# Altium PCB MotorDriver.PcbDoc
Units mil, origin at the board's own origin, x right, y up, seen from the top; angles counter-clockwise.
Board outline 4000 x 4995 mil, 4 copper layers (Top Layer, VCC, GND, Bottom Layer), stack 23.756 mil thick; 93 components, 73 nets, 281 pads, 38 vias.
Unrouted connection lines stored in the file: 23.
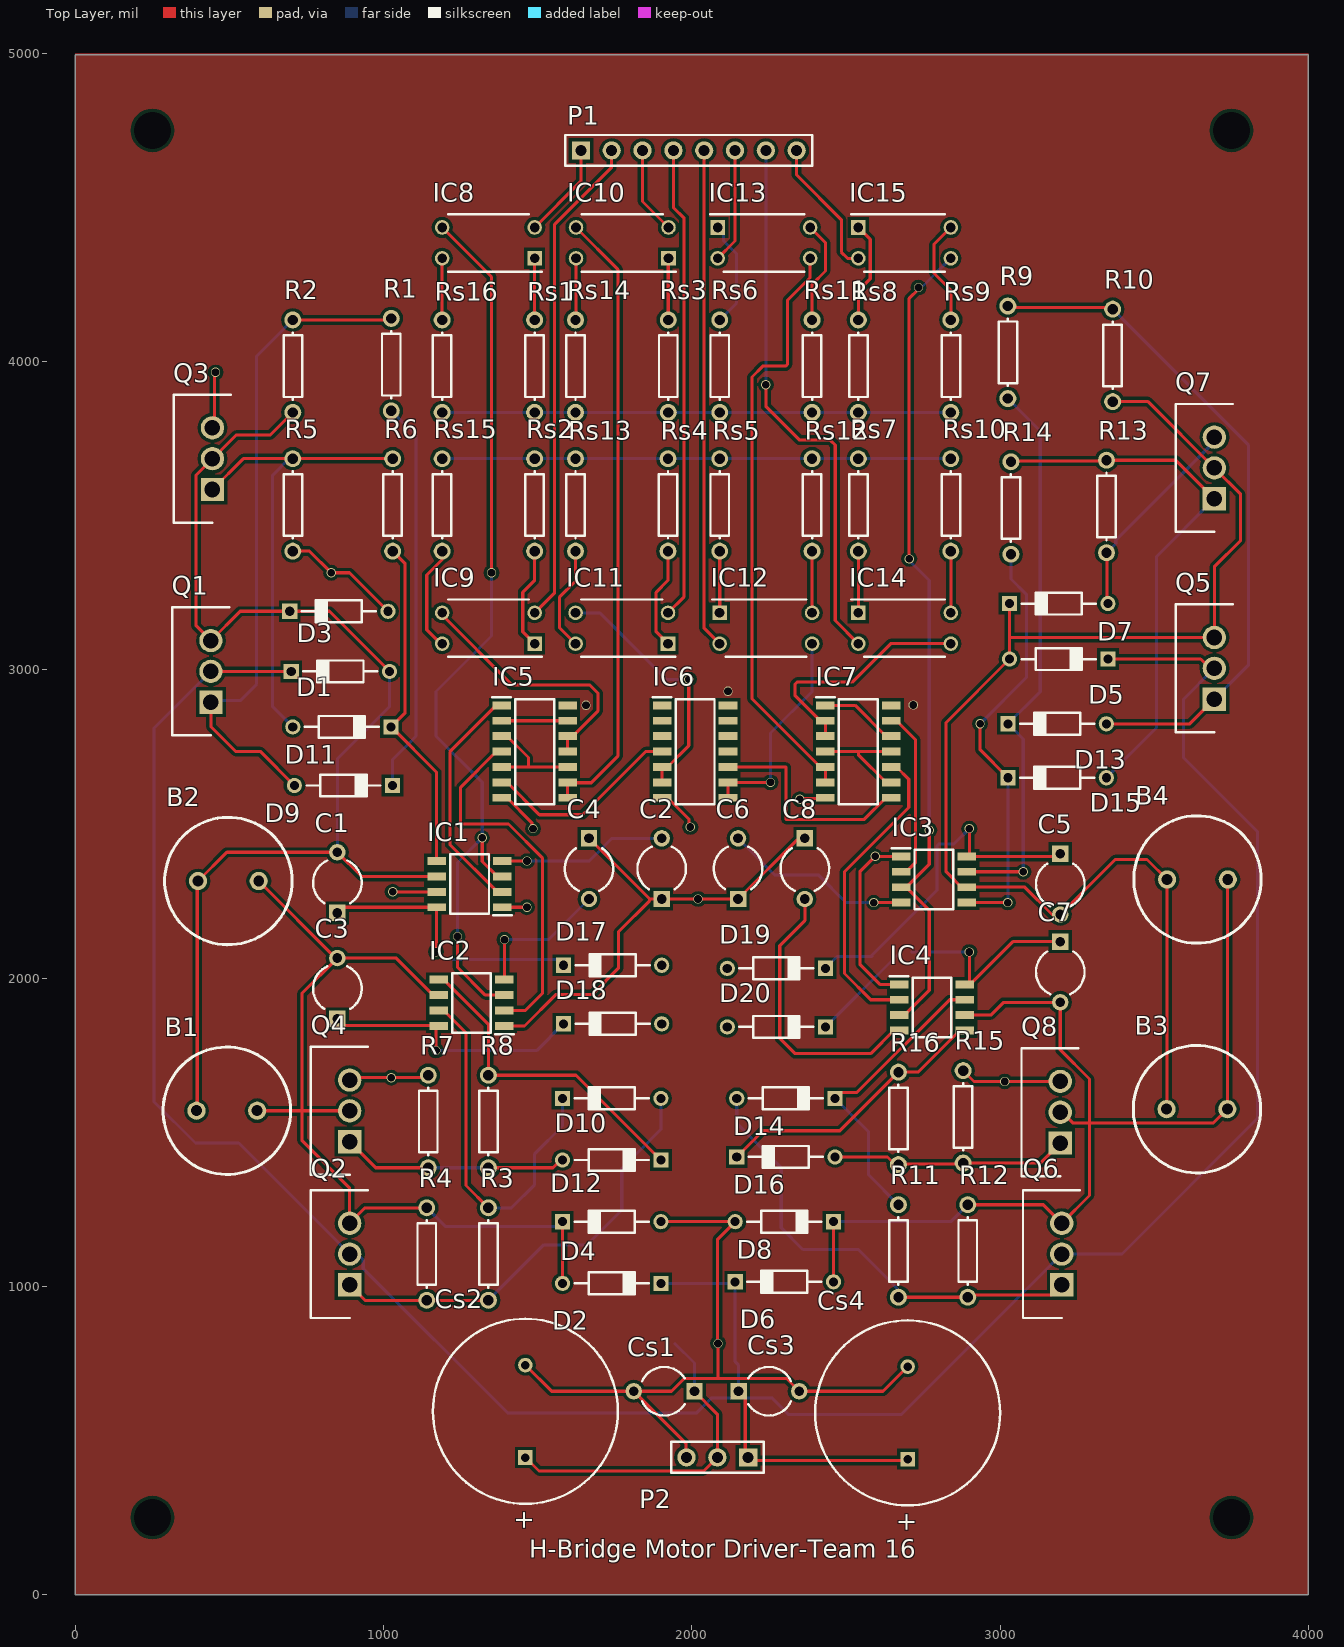
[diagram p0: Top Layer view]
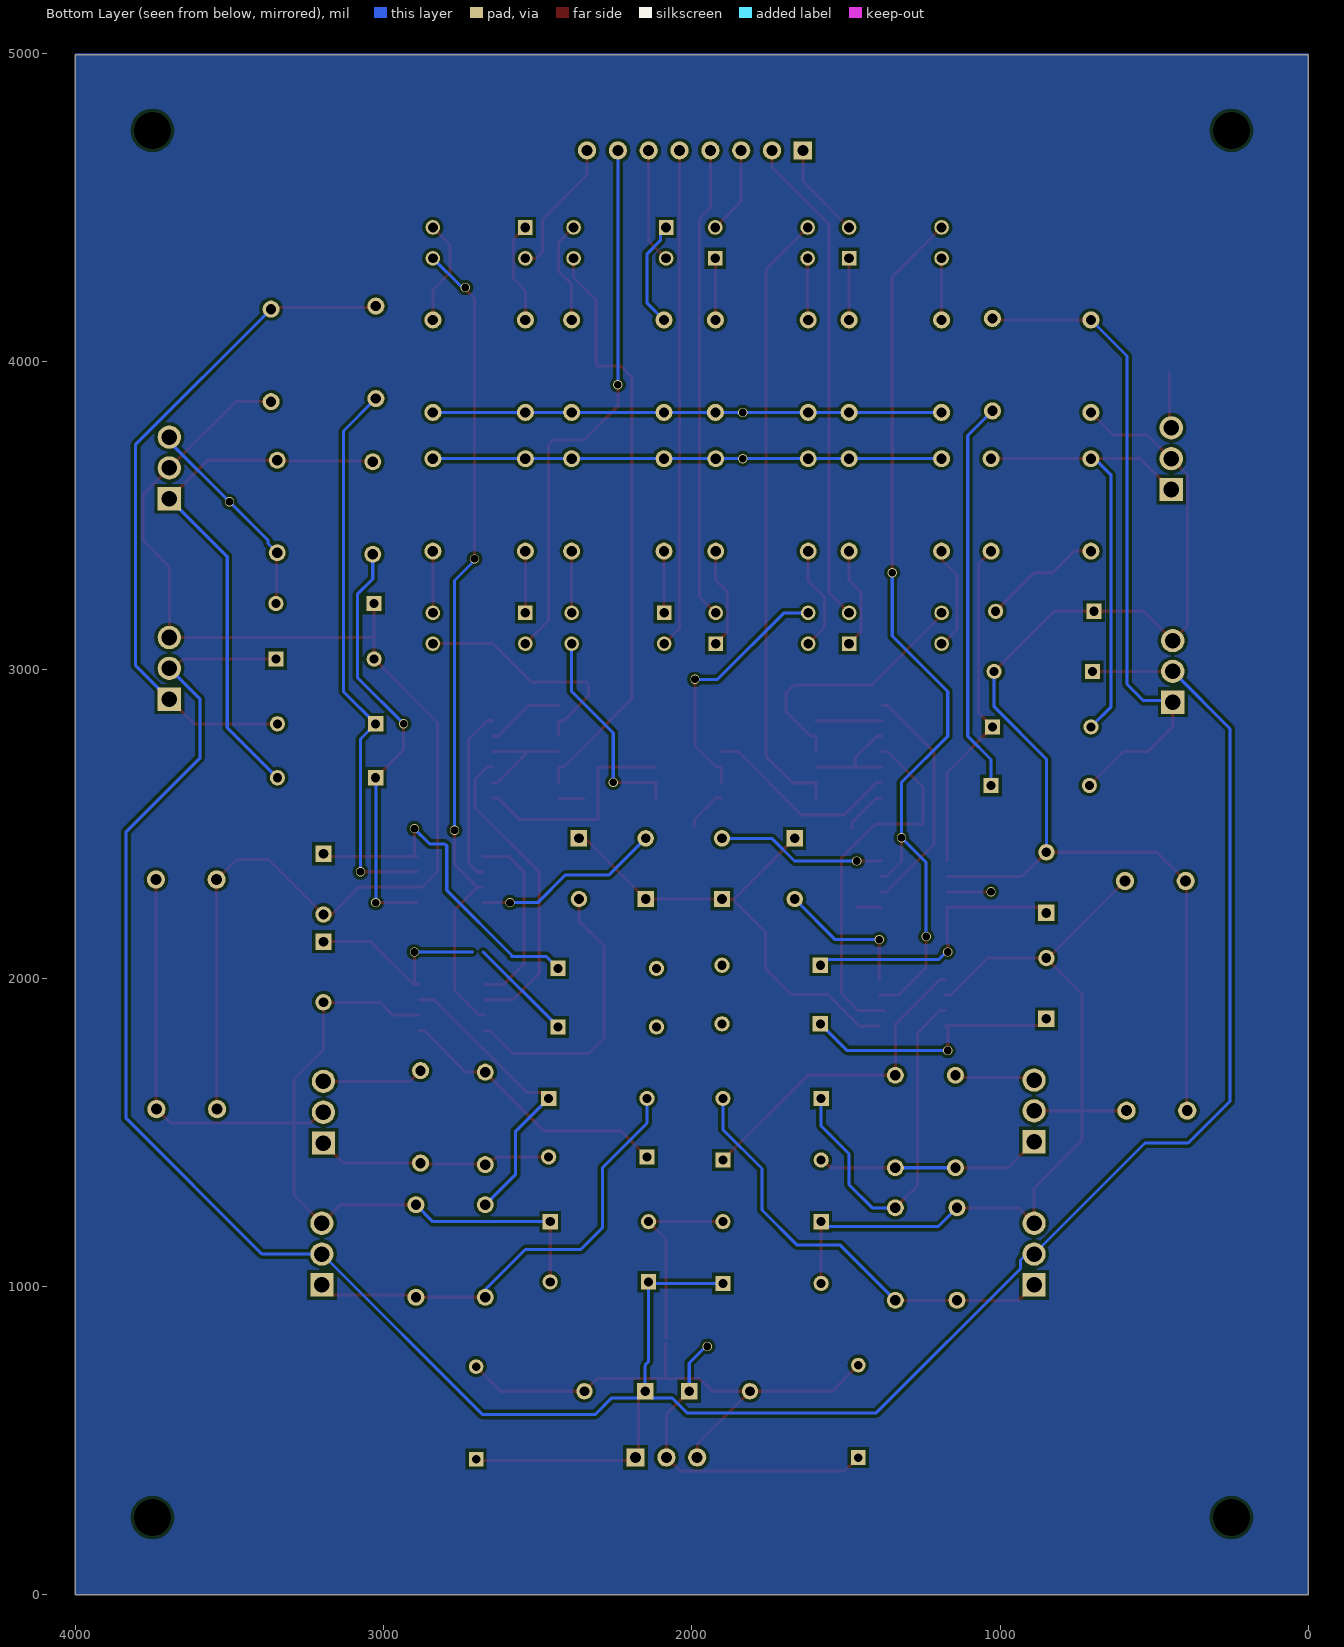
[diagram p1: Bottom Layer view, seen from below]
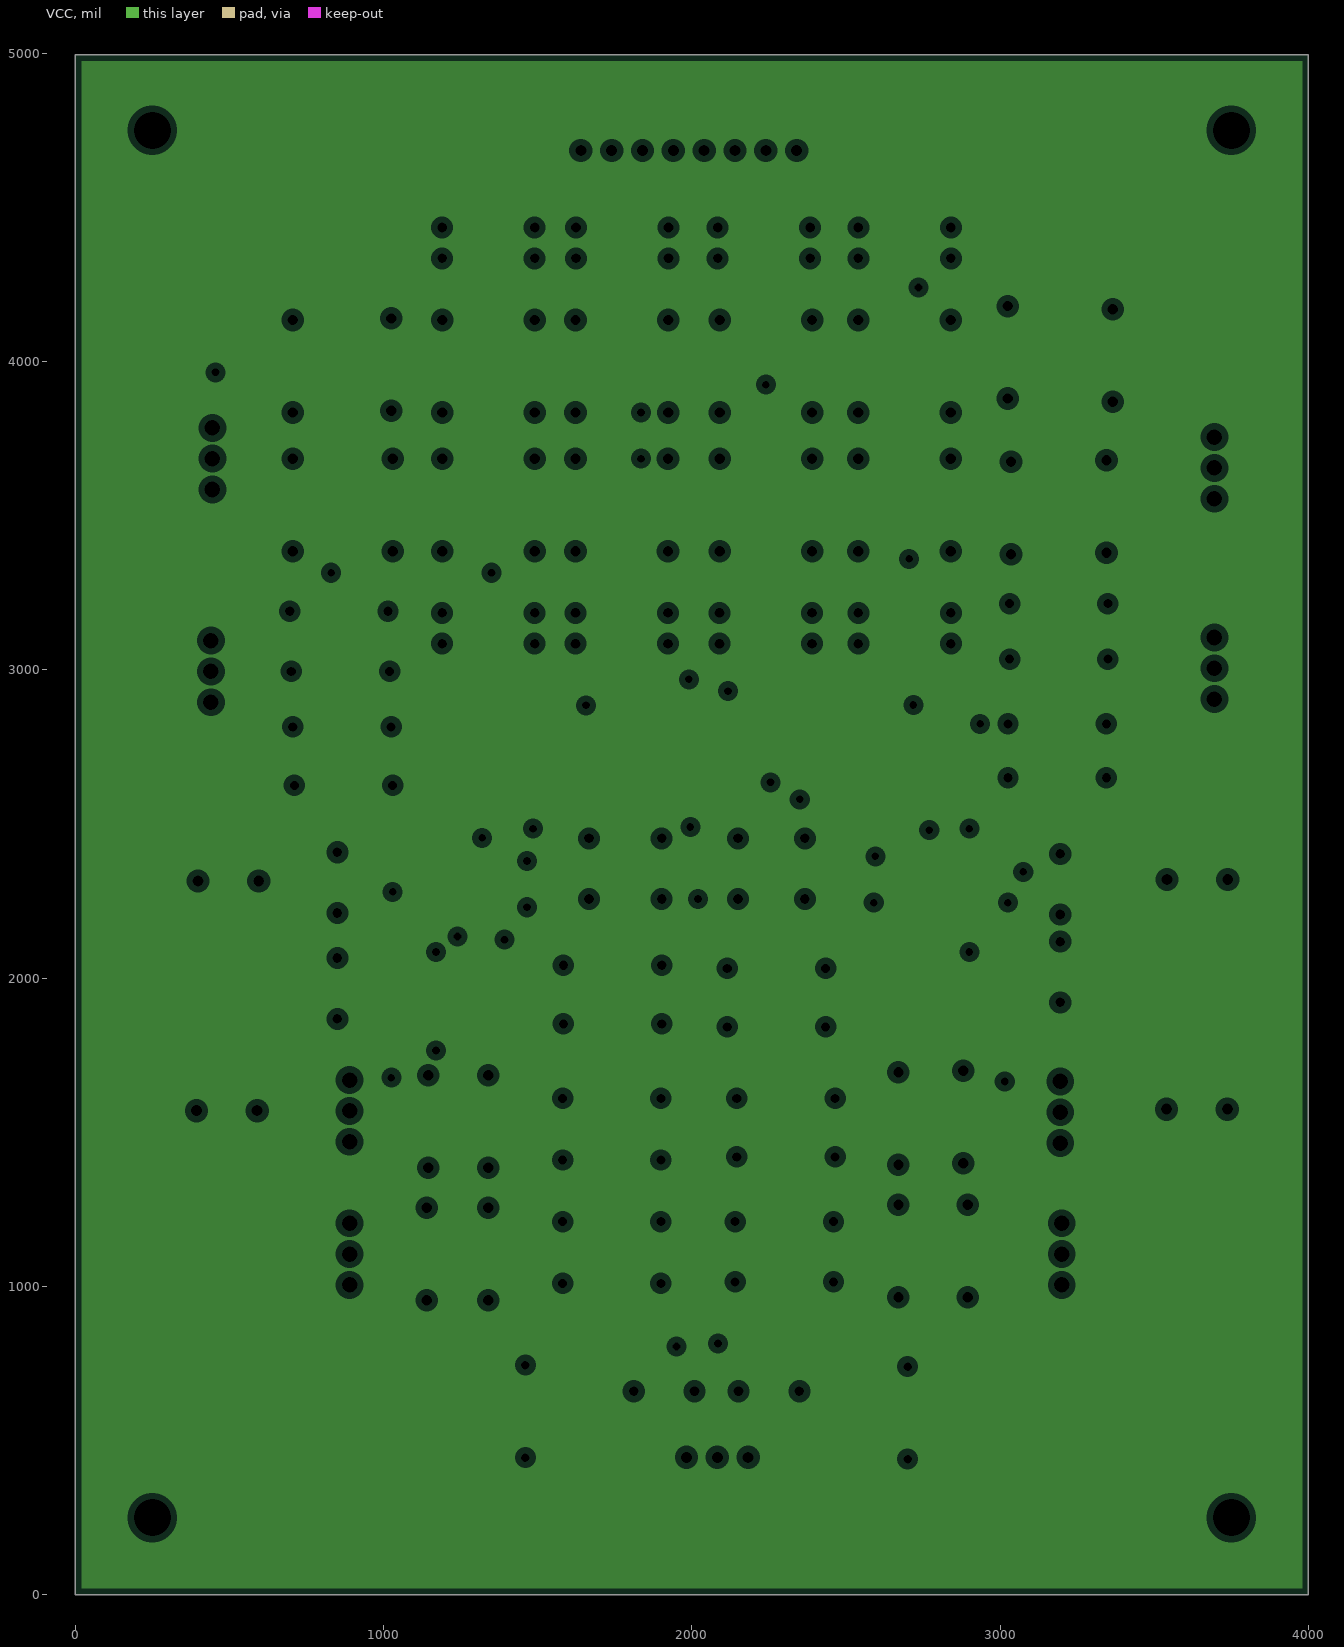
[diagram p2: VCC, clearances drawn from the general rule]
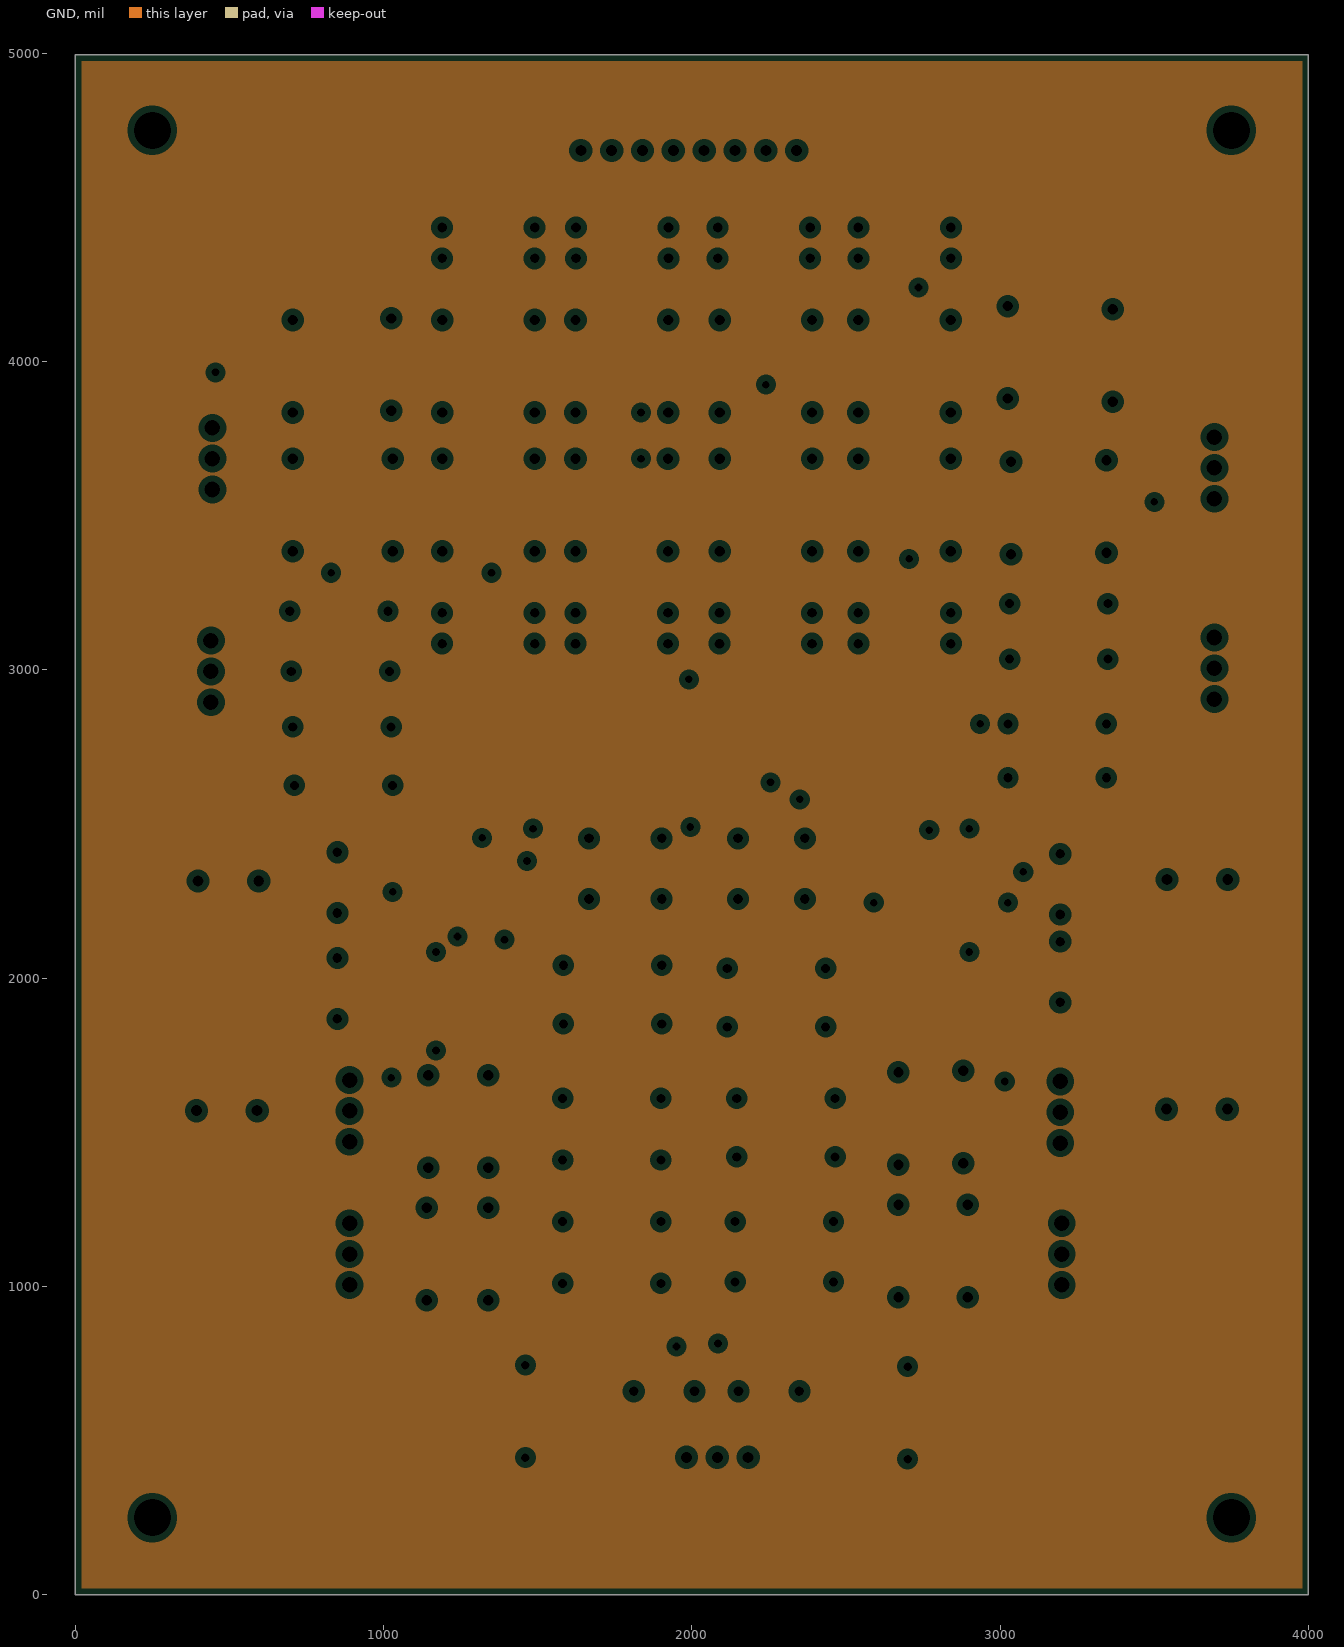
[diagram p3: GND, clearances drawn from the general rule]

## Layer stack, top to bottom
Top Solder: solder mask 0.4, Solder Resist, Dk 3.5
Top Layer: signal copper 1.4
Dielectric 2: prepreg 2.8, PP-006, Dk 4.1
VCC: plane copper 1.3778
Dielectric 1: dielectric 12.6, FR-4, Dk 4.8
GND: plane copper 1.3778
Dielectric 3: prepreg 2.8, PP-006, Dk 4.1
Bottom Layer: signal copper 1.4
Bottom Solder: solder mask 0.4, Solder Resist, Dk 3.5

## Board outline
0,0 4000,0 4000,4995 0,4995

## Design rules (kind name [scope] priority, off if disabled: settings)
Clearance [All] p1: gap=10 ignorepadtopadclearanceinfootprint=FALSE except(0: Arc-Hole Track-Hole SMDPad-Hole THPad-Hole Via-Hole Fill-Hole Poly-Hole Region-Hole Text-Hole)
PlaneClearance [All] p1: clearance=20
PlaneConnect [All] p1: planeconnectstyle=Relief reliefexpansion=20 reliefentries=4 reliefconductorwidth=10 reliefairgap=10
PolygonConnect [All] p1: connectstyle=Relief reliefconductorwidth=10 reliefentries=4 polygonreliefangle="90 Angle" airgapwidth=10
RoutingVias [All] p1: holewidth=28 width=50 viastyle="Through Hole" minholewidth=28 minwidth=50 maxholewidth=28 maxwidth=50
SolderMaskExpansion [All] p1: expansion=4
Width [All] p1: maxlimit=10 minlimit=10 preferedwidth=10
28 further rules are at their usual default settings.

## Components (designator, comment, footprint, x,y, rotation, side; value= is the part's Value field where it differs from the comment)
B1 "Motor" RB5-10.5 491.57,1570 r0 top
B2 "Motor" RB5-10.5 496.57,2315 r0 top
B3 "Motor" RB5-10.5 3638.43,1575 r0 top
B4 "Motor" RB5-10.5 3640,2320 r0 top
C1 "" CAPR5-4X5 850,2310 r90 top value=1.5uF
C2 "" CAPR5-4X5 1902.2,2355 r90 top value=100nF
C3 "" CAPR5-4X5 850,1966.57 r90 top value=1.5uF
C4 "" CAPR5-4X5 1666.38,2355 r270 top value=100nF
C5 "" CAPR5-4X5 3195,2305 r270 top value=1.5uF
C6 "" CAPR5-4X5 2149.92,2355 r90 top value=100nF
C7 "" CAPR5-4X5 3195,2020 r270 top value=1.5uF
C8 "" CAPR5-4X5 2366.38,2355 r270 top value=100nF
Cs1 "" CAPR5-4X5 1910,660 r180 top value=100nF
Cs2 "" RB7.6-15 1460,595 r270 top value=100uF
Cs3 "" CAPR5-4X5 2250,660 r0 top value=100nF
Cs4 "" RB7.6-15 2700,590 r270 top value=100uF
D1 "1N5711" DIOAD810W51L378D176P 860,2995 r0 top
D2 "1N5711" DIOAD810W51L378D176P 1740,1010 r180 top
D3 "1N5711" DIOAD810W51L378D176P 855,3190 r0 top
D4 "1N5711" DIOAD810W51L378D176P 1740,1210 r0 top
D5 "1N5711" DIOAD810W51L378D176P 3190,3035 r180 top
D6 "1N5711" DIOAD810W51L378D176P 2300,1015 r0 top
D7 "1N5711" DIOAD810W51L378D176P 3190,3215 r0 top
D8 "1N5711" DIOAD810W51L378D176P 2300,1210 r180 top
D9 "1N5711" DIOAD810W51L378D176P 870,2625 r180 top
D10 "1N5711" DIOAD810W51L378D176P 1740,1610 r0 top
D11 "1N5711" DIOAD810W51L378D176P 865,2815 r180 top
D12 "1N5711" DIOAD810W51L378D176P 1740,1410 r180 top
D13 "1N5711" DIOAD810W51L378D176P 3185,2825 r0 top
D14 "1N5711" DIOAD810W51L378D176P 2305,1610 r180 top
D15 "1N5711" DIOAD810W51L378D176P 3185,2650 r0 top
D16 "1N5711" DIOAD810W51L378D176P 2305,1420 r0 top
D17 "1N5711" DIOAD810W51L378D176P 1742.76,2041.85 r0 top
D18 "1N5711" DIOAD810W51L378D176P 1742.76,1851.85 r0 top
D19 "1N5711" DIOAD810W51L378D176P 2274.37,2031.85 r180 top
D20 "1N5711" DIOAD810W51L378D176P 2274.37,1841.85 r180 top
IC1 "IR2104SPBF" SOIC127P600X175-8N 1278.98,2305 r180 top
IC2 "IR2104SPBF" SOIC127P600X175-8N 1285.28,1920 r180 top
IC3 "IR2104SPBF" SOIC127P600X175-8N 2785.28,2320 r0 top
IC4 "IR2104SPBF" SOIC127P600X175-8N 2778.98,1905 r0 top
IC5 "SN74HC02D" SOIC127P600X175-14N 1490,2735 r0 top
IC6 "SN74HC02D" SOIC127P600X175-14N 2010.47,2735 r0 top
IC7 "SN74HC02D" SOIC127P600X175-14N 2540,2735 r0 top
IC8 "TLP521-1" DIP762W60P254L448H380Q4N 1340,4385 r180 top
IC9 "TLP521-1" DIP762W60P254L448H380Q4N 1340,3135 r180 top
IC10 "TLP521-1" DIP762W60P254L448H380Q4N 1774.25,4385 r180 top
IC11 "TLP521-1" DIP762W60P254L448H380Q4N 1772.68,3135 r180 top
IC12 "TLP521-1" DIP762W60P254L448H380Q4N 2240,3135 r0 top
IC13 "TLP521-1" DIP762W60P254L448H380Q4N 2233.7,4385 r0 top
IC14 "TLP521-1" DIP762W60P254L448H380Q4N 2690,3135 r0 top
IC15 "TLP521-1" DIP762W60P254L448H380Q4N 2690,4385 r0 top
P1 "Header 8" HDR1X8 1640,4685 r0 top
P2 "Header 3" HDR1X3 2182.68,445.55 r180 top
Q1 "IRF3205S" TO254P469X1042X1930-3P 440,2895 r90 top
Q2 "IRF3205S" TO254P469X1042X1930-3P 890,1005 r90 top
Q3 "IRF3205S" TO254P469X1042X1930-3P 445,3585 r90 top
Q4 "IRF3205S" TO254P469X1042X1930-3P 890,1469.45 r90 top
Q5 "IRF3205S" TO254P469X1042X1930-3P 3695,2905 r90 top
Q6 "IRF3205S" TO254P469X1042X1930-3P 3200,1005 r90 top
Q7 "IRF3205S" TO254P469X1042X1930-3P 3695,3555 r90 top
Q8 "IRF3205S" TO254P469X1042X1930-3P 3195,1465 r90 top
R1 "" AXIAL-0.3 1025,3990 r90 top value=20
R2 "" AXIAL-0.3 705.55,3985 r270 top value=10K
R3 "" AXIAL-0.3 1340,1105 r90 top value=20
R4 "" AXIAL-0.3 1140,1105 r270 top value=10K
R5 "" AXIAL-0.3 705.55,3535 r270 top value=10K
R6 "" AXIAL-0.3 1029.45,3535 r90 top value=20
R7 "" AXIAL-0.3 1145,1535 r270 top value=10K
R8 "" AXIAL-0.3 1340,1535 r90 top value=20
R9 "" AXIAL-0.3 3025,4030 r90 top value=20
R10 "" AXIAL-0.3 3365,4020 r270 top value=10K
R11 "" AXIAL-0.3 2670,1115 r90 top value=20
R12 "" AXIAL-0.3 2895,1115 r270 top value=10K
R13 "" AXIAL-0.3 3345,3530 r270 top value=10K
R14 "" AXIAL-0.3 3035,3525 r90 top value=20
R15 "" AXIAL-0.3 2880,1550 r270 top value=10K
R16 "" AXIAL-0.3 2670,1545 r90 top value=20
Rs1 "" AXIAL-0.3 1490,3985 r270 top value=1K
Rs2 "" AXIAL-0.3 1490,3535 r90 top value=1K
Rs3 "" AXIAL-0.3 1923.46,3985 r270 top value=1K
Rs4 "" AXIAL-0.3 1922.68,3535 r90 top value=1K
Rs5 "" AXIAL-0.3 2090.47,3535 r90 top value=1K
Rs6 "" AXIAL-0.3 2090.47,3985 r270 top value=1K
Rs7 "" AXIAL-0.3 2540,3535 r90 top value=1K
Rs8 "" AXIAL-0.3 2540,3985 r270 top value=1K
Rs9 "" AXIAL-0.3 2840,3985 r90 top value=1K
Rs10 "" AXIAL-0.3 2840,3535 r270 top value=1K
Rs11 "" AXIAL-0.3 2390,3985 r90 top value=1K
Rs12 "" AXIAL-0.3 2390,3535 r270 top value=1K
Rs13 "" AXIAL-0.3 1622.68,3535 r270 top value=1K
Rs14 "" AXIAL-0.3 1622.68,3985 r90 top value=1K
Rs15 "" AXIAL-0.3 1190,3535 r270 top value=1K
Rs16 "" AXIAL-0.3 1190,3985 r90 top value=1K

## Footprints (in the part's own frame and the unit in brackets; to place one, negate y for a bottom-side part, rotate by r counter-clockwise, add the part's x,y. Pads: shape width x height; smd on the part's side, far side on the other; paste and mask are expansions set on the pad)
AXIAL-0.3 [mm] "Axial Device, Thru-Hole; 2 Leads; 0.3 in Pin Spacing"
  round 1.4 hole 0.85: 1(-3.81,0) 2(3.81,0)
  silkscreen extent -2.77,-0.76 2.77,0.76
CAPR5-4X5 [mm] "Capacitor; 2 Leads"
  rect 1.35x1.35 hole 0.8: 1(-2.5,0)
  round 1.35 hole 0.8: 2(2.5,0)
  silkscreen extent -1.69,-2 1.82,2
DIOAD810W51L378D176P [mm]
  rect 1.25x1.25 hole 0.75: 1(-4.05,0)
  round 1.25 hole 0.75: 2(4.05,0)
  silkscreen extent -3.05,-0.9 3.05,0.9
DIP762W60P254L448H380Q4N [mm]
  rect 1.2x1.2 hole 0.8: 1(-3.81,1.27)
  round 1.2 hole 0.8: 2(-3.81,-1.27) 3(3.81,-1.27) 4(3.81,1.27)
  silkscreen extent -4.41,-2.36 3.32,2.36, body extent -3.96,-2.24 3.96,2.24, height 3.8
HDR1X3 [mm] "Connector; Header; 3 Position"
  rect 1.5x1.5 hole 0.9: 1(0,0)
  round 1.5 hole 0.9: 2(2.54,0) 3(5.08,0)
  silkscreen extent -1.27,-1.27 6.35,1.27
HDR1X8 [mm] "Connector; Header; 8 Position"
  rect 1.5x1.5 hole 0.9: 1(0,0)
  round 1.5 hole 0.9: 2(2.54,0) 3(5.08,0) 4(7.62,0) 5(10.16,0) 6(12.7,0) 7(15.24,0) 8(17.78,0)
  silkscreen extent -1.27,-1.27 19.05,1.27
RB5-10.5 [mm] "Capacitor (Radial); 2 Leads"
  round 1.5 hole 0.9: 1(-2.5,0) 2(2.5,0)
  silkscreen extent -5.25,-5.25 5.25,5.25
RB7.6-15 [mm] "Polarized Capacitor (Radial); 2 Leads"
  rect 1.2x1.2 hole 0.7: 1(3.81,0)
  round 1.2 hole 0.7: 2(-3.81,0)
  silkscreen extent -7.62,-7.62 7.62,7.62
SOIC127P600X175-8N [mm]
  rect 1.525x0.65 smd: 1(-2.712,1.905) 2(-2.712,0.635) 3(-2.712,-0.635) 4(-2.712,-1.905) 5(2.712,-1.905) 6(2.712,-0.635) 7(2.712,0.635) 8(2.712,1.905)
  silkscreen extent -3.47,-2.45 1.6,2.58, body extent -3,-2.45 3,2.45, height 1.75
SOIC127P600X175-14N [mm]
  rect 1.525x0.65 smd: 1(-2.712,3.81) 2(-2.712,2.54) 3(-2.712,1.27) 4(-2.712,0) 5(-2.712,-1.27) 6(-2.712,-2.54) 7(-2.712,-3.81) 8(2.712,-3.81) 9(2.712,-2.54) 10(2.712,-1.27) 11(2.712,0) 12(2.712,1.27) 13(2.712,2.54) 14(2.712,3.81)
  silkscreen extent -3.47,-4.33 1.6,4.48, body extent -3,-4.33 3,4.33, height 1.75
TO254P469X1042X1930-3P [mm]
  rect 1.92x1.92 hole 1.28: 1(0,0)
  round 1.92 hole 1.28: 2(2.54,0) 3(5.08,0)
  silkscreen extent -2.73,-1.5 7.81,3.19, body extent -2.67,-1.5 7.75,3.19, height 18.84

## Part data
B1 B2 B3 B4: "Motor, General Kind"
C1 C2 C3 C4 C5 C6 C7 C8 Cs1 Cs3: library part Cap2, "Capacitor"
Cs2 Cs4: library part "Cap Pol1", "Polarized Capacitor (Radial)"
D1 D2 D3 D4 D5 D6 D7 D8 D9 D10 D11 D12 D13 D14 D15 D16 D17 D18 D19 D20: "Diode", Manufacturer_Name=STMicroelectronics, Mouser Part Number=511-1N5711, RS Part Number=6870763
IC1 IC2 IC3 IC4: "Integrated Circuit", Manufacturer_Name=Infineon, Mouser Part Number=942-IR2104SPBF, RS Part Number=9194961
IC5 IC6 IC7: "Integrated Circuit", Manufacturer_Name="Texas Instruments", Mouser Part Number=595-SN74HC02D, RS Part Number=6631874P
IC8 IC9 IC10 IC11 IC12 IC13 IC14 IC15: "Integrated Circuit", Manufacturer_Name=Toshiba, RS Part Number=6258665
P1: "Header, 8-Pin"
P2: "Header, 3-Pin"
Q1 Q2 Q3 Q4 Q5 Q6 Q7 Q8: "MOSFET (N-Channel)", Manufacturer_Name="International Rectifier", RS Part Number=3954859
R1 R2 R3 R4 R5 R6 R7 R8 R9 R10 R11 R12 R13 R14 R15 R16 Rs1 Rs2 Rs3 Rs4 Rs5 Rs6 Rs7 Rs8 Rs9 Rs10 Rs11 Rs12 Rs13 Rs14 Rs15 Rs16: library part Res1, "Resistor"

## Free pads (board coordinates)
  round 0 hole 120: 2(250,4750) 3(3750,4750) 4(250,250) 5(3750,250)

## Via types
v1: diameter 30, hole 25, Top Layer to Bottom Layer, 20 vias
v2: diameter 30, hole 25, Top Layer to GND, 8 vias
v3: diameter 30, hole 25, Top Layer to VCC, 6 vias
v4: diameter 30, hole 25, VCC to Bottom Layer, 3 vias
v5: diameter 30, hole 25, GND to Bottom Layer, 1 vias

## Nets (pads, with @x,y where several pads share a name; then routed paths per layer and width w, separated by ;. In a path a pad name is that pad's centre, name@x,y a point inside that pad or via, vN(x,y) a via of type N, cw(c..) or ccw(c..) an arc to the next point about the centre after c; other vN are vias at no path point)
GND: Cs1.2 Cs2.2 Cs3.2 Cs4.2 D3.2 D4.2 D7.2 D8.2 IC5.7 IC6.7 IC7.7 P2.3 Q3.3 Q4.3 Q7.3 Q8.3 R5.2 R7.1 R13.2 R15.1 | length 4618
  Top Layer w10: Q3.3 451.17,3791.17 451.17,3961.17 v2(455,3965) ; R5.2 760,3385 v2(830,3315) 889.45,3315 D3.2 ; Q4.3 897.78,1677.22 1137.22,1677.22 R7.1 ; IC5.7 1400.45,2585 1481.17,2504.28 1481.17,2488.83 v2(1485,2485) ; Cs2.2 1545,660 Cs1.2 ; D4.2 D8.2 2083.7,1153.15 2083.7,831.3 ; IC6.7 1920.92,2585 1991.17,2514.75 1991.17,2493.83 v2(1995,2490) ; P2.3@1983.46,446.34 P2.3 1981.5,446.73 1981.5,490.08 Cs1.2 ; v2(2085,815) 2085,701.58 ; v2(2350,2580) 2352.5,2582.5 2430.73,2582.5 IC7.7 ; Cs4.2 2620,660 Cs3.2 2306.85,701.58 2085,701.58 ; R15.1 2915,1665 Q8.3 ; R13.2 3347.22,3377.78 3347.22,3217.22 D7.2 ; Cs1.2 1934.06,660 1975.64,701.58 2085,701.58
  Bottom Layer w10: R13.2 3375.09,3410.09 3375.09,3420.09 v5(3500,3545) 3695,3740 Q7.3
  other v2: 3015,1665 1025,1677.22
NetB1_1: B1.1 B2.1 C1.2 D1.2 D3.1 IC1.6 Q1.3 Q3.2 R2.2 | length 3924.2
  Top Layer w10: B1.1 395.65,1572.5 395.65,2312.5 B2.1 491.57,2408.43 C1.2 928.43,2330 IC1.6 ; R2.2 632.51,3761.96 521.96,3761.96 Q3.2 392.2,3632.2 392.2,3142.8 Q1.3 535,3190 D3.1 824.45,3190 D1.2
  Bottom Layer w10: C1.2 850,2710.98 1019.45,2880.43 D1.2 ; D1.2@1019.45,3010 D1.2@1034.45,2995
NetB1_2: B1.2 B2.2 C3.2 D2.2 D4.1 IC2.6 Q2.3 Q4.2 R4.1 | length 2951.2
  Top Layer w10: B1.2 590.28,1569.72 735,1569.72 ; B2.2 845,2065 C3.2 ; Q4.2 889.72,1569.72 735,1569.72 ; R4.1 940,1255 Q2.3 890,1318.74 735,1473.74 735,1569.72 ; IC2.6 1161.28,1945 1041.28,2065 C3.2 ; D2.2 D4.1 ; 735,1569.72 735,1950 C3.2
  Bottom Layer w10: R4.1 1200,1195 1565.55,1195 D4.1
NetB3_1: B3.1 B4.1 C5.2 D5.2 D7.1 IC3.6 Q5.3 Q7.2 R10.2 | length 4279.6
  Top Layer w10: D7.1 3030.55,3105 ; R10.2 3480,3870 Q7.2 3780,3570 3780,3419.48 3695,3334.48 Q5.3 3030.55,3105 ; B3.1 3541.57,1576.57 B4.1 3476.57,2385 3373.43,2385 C5.2 3168.43,2206.57 3080,2295 IC3.6 2874.82,2295 2852.89,2316.94 2852.89,2317.11 2825,2345 2825,2829.45 D5.2 3030.55,3105
NetB3_2: B3.2 B4.2 C7.2 D6.2 D8.1 IC4.6 Q6.3 Q8.2 R12.1 | length 3423.1
  Top Layer w10: D6.2 D8.1 ; IC4.6 2970,1880 3011.57,1921.57 C7.2 3195,1767.69 3290,1672.69 3290,1530.47 ; R12.1 3140,1265 Q6.3 3290,1295 3290,1530.47 ; Q8.2 3200.61,1565 3235.14,1530.47 3290,1530.47 ; B4.2 3737.64,2319.21 3737.64,1575.79 B3.2 3692.32,1530.47 3290,1530.47
  Bottom Layer w10: D8.1 2840,1210 R12.1
NetC1_1: C1.1 D17.1 IC1.8 | length 906.9
  Top Layer w10: C1.1 868.43,2230 IC1.8 1172.2,2117.2 1170,2115 v1(1170,2085)
  Bottom Layer w10: v1(1170,2085) 1175,2085 1200,2060 1565.16,2060 D17.1
NetC2_2: C2.2 IC1.4 | length 546.9
  Top Layer w10: IC1.4 v1(1465,2380)
  Bottom Layer w10: v1(1465,2380) 1667.32,2380 1740.74,2453.43 C2.2
NetC3_1: C3.1 D18.1 IC2.8 | length 871.3
  Top Layer w10: C3.1 871.57,1846.57 1176.93,1846.57 IC2.8 1177.8,1845 1170,1837.2 v1(1170,1765)
  Bottom Layer w10: v1(1170,1765) 1496.46,1765 D18.1
NetC4_2: C4.2 IC2.4 | length 460.5
  Top Layer w10: IC2.4 1390,1997.05 1392.05,1999.09 v1(1392.05,2125)
  Bottom Layer w10: v1(1392.05,2125) 1534.8,2125 C4.2
NetC5_1: C5.1 D19.1 IC3.8 | length 1143
  Top Layer w10: IC3.8 IC3.8@2892.2,2395 ; v1(2900,2485) 2900,2402.8 IC3.8@2892.2,2395 ; C5.1 3186.58,2395 IC3.8@2892.2,2395
  Bottom Layer w10: D19.1 2471.97,2070 2580,2070 ; 2585,2070 2580,2070 ; v1(2900,2485) 2850,2435 2800.86,2435 2795,2429.14 2795,2285 2580,2070
NetC6_2: C6.2 IC3.4 | length 614.9
  Top Layer w10: v1(2590,2245) IC3.4
  Bottom Layer w10: C6.2 2268.35,2335 2410,2335 2500,2245 v1(2590,2245)
NetC7_1: C7.1 D20.1 IC4.8 | length 1006.7
  Top Layer w10: IC4.8 IC4.8@2892.2,1980 ; v1(2900,2085) 2900,1987.8 IC4.8@2892.2,1980 ; C7.1 3041.4,2118.43 2902.97,1980 IC4.8@2892.2,1980
  Bottom Layer w10: D20.1 2676.97,2085 ; 2711.97,2085 v1(2900,2085)
NetC8_2: C8.2 IC4.4 | length 924.3
  Top Layer w10: C8.2 2366.38,2186.38 2285,2105 2285,1805 2335,1755 2579.98,1755 2654.98,1830 IC4.4
NetD9_1: D9.1 IC1.7 R1.1 | length 1422.2
  Top Layer w10: v1(1029.45,2280) IC1.7
  Bottom Layer w10: R1.1 1105,3760 1105,2785 1029.45,2709.45 D9.1
NetD9_2: D9.2 Q1.1 R1.2 R2.1 | length 2160.6
  Top Layer w10: Q1.1 440,2815 519.45,2735.55 600,2735.55 D9.2 ; R2.1@703.05,4137.5 R2.1 1020,4135 R1.2 R1.2@1027.5,4137.5
  Bottom Layer w10: Q1.1 445,2900 535,2900 588.46,2953.46 588.46,4017.91 R2.1
NetD10_1: D10.1 IC2.7 R3.2 | length 1215.6
  Top Layer w10: IC2.7 1195.73,1895 1267.45,1823.28 1267.45,1327.55 R3.2
  Bottom Layer w10: R3.2 1415,1255 1490,1330 1490,1430 1580.55,1520.55 D10.1
NetD10_2: D10.2 Q2.1 R3.1 R4.2 | length 1439.5
  Top Layer w10: Q2.1 940,955 R4.2 R3.1
  Bottom Layer w10: R3.1 1520,1135 1660,1135 1772.68,1247.68 1772.68,1382.32 1899.45,1509.09 D10.2
NetD11_1: D11.1 IC1.5 R6.1 | length 1101.9
  Top Layer w10: R6.1 1070,3344.45 1070,2860.55 D11.1 1172.2,2667.24 IC1.5
NetD11_2: D11.2 Q3.1 R5.1 R6.2 | length 1562.3
  Top Layer w10: Q3.1 545,3685 R5.1 R6.2 R6.2@1029.45,3680
  Bottom Layer w10: D11.2 640,2880.55 640,3631.66 693.34,3685 R5.1
NetD12_1: D12.1 IC2.5 R8.2 | length 1060.3
  Top Layer w10: IC2.5 1195.73,1995 1340,1850.73 R8.2 1624.45,1685 D12.1
NetD12_2: D12.2 Q4.1 R7.2 R8.1 | length 735.9
  Top Layer w10: Q4.1 974.45,1385 R7.2 ; R8.1 1549.54,1385 1574.54,1410 D12.2
  Bottom Layer w10: R7.2 R8.1
NetD13_1: D13.1 IC3.7 R9.1 | length 1825.2
  Top Layer w10: IC3.7 v1(3075,2345)
  Bottom Layer w10: R9.1 3130,3775 3130,2929.45 D13.1 3075,2775.55 v1(3075,2345)
NetD13_2: D13.2 Q5.1 R9.2 R10.1 | length 2220.6
  Top Layer w10: R9.2 3030,4175 3360,4175 R10.1 ; D13.2 3615,2825 Q5.1
  Bottom Layer w10: R10.1 3805,3730 3805,3015 Q5.1
NetD14_1: D14.1 IC4.7 R11.2 | length 984
  Top Layer w10: D14.1 2484.06,1629.61 2535.84,1629.61 2836.23,1930 IC4.7
  Bottom Layer w10: D14.1 2572.71,1501.74 2572.71,1362.29 R11.2
NetD14_2: D14.2 Q6.1 R11.1 R12.2 | length 1514.2
  Top Layer w10: R11.1 R12.2 2902.2,972.2 3167.2,972.2 Q6.1
  Bottom Layer w10: D14.2 2145.55,1529.45 2290,1385 2290,1190 2360,1120 2540,1120 2670,990 R11.1
NetD15_1: D15.1 IC3.5 R14.1 | length 1383.5
  Top Layer w10: IC3.5 v1(3025,2245) ; v1(2935,2825) 2935,2740.55 D15.1
  Bottom Layer w10: v1(2935,2825) 3085,2975 3085,3245 3035,3295 R14.1 ; v1(3025,2245) 3025,2649.45 D15.1
NetD15_2: D15.2 Q7.1 R13.1 R14.2 | length 1764.1
  Top Layer w10: R14.2 3037.5,3677.5 3342.5,3677.5 R13.1 3570,3680 Q7.1
  Bottom Layer w10: D15.2 3507.08,2812.63 3507.08,3367.08 Q7.1
NetD16_1: D16.1 IC4.5 R16.2 | length 910
  Top Layer w10: D16.1 2230.55,1505 2480,1505 R16.2 2733.52,1695 2868.52,1830 IC4.5
NetD16_2: D16.2 Q8.1 R15.2 R16.1 | length 769.9
  Top Layer w10: D16.2 2634.81,1420 2659.81,1395 R16.1 2672.5,1397.5 2877.5,1397.5 R15.2 3130,1400 Q8.1
NetIC1_2: IC1.2 IC5.1 | length 765.6
  Top Layer w10: IC5.1 1366,2885 1215,2734 1215,2433.52 1368.52,2280 IC1.2
NetIC1_3: IC1.3 IC2.3 IC8.3 | length 2987.8
  Top Layer w10: IC8.3 1350,4275 v1(1350,3315) ; v1(1240,2135) 1240,2035 1330,1945 IC2.3 ; v1(1320,2455) 1320,2378.52 1368.52,2330 IC1.3
  Bottom Layer w10: v1(1240,2135) 1240,2375 v1(1320,2455) 1320,2635 1170,2785 1170,2930 1350,3110 v1(1350,3315)
NetIC2_2: IC2.2 IC5.4 | length 1213.8
  Top Layer w10: IC2.2@1374.82,1895 IC2.2 1460,1895 1515,1950 1515,2390 1405,2500 1250,2500 1250,2619 1366,2735 IC5.4
NetIC3_2: IC3.2 IC7.13 | length 561.8
  Top Layer w10: IC7.13 2664,2835 2725,2774 2725,2374.27 2695.73,2345 IC3.2
NetIC3_3: IC3.3 IC4.3 IC15.3 | length 2656
  Top Layer w10: IC4.3 2689.43,1880 2770,1960.57 2770,2220.73 IC3.3@2695.73,2295 ; IC3.3 IC3.3@2695.73,2295 ; v1(2705,3360) 2705,4205 v1@2735,4235 ; v1(2770,2480) 2770,2369.27 IC3.3@2695.73,2295
  Bottom Layer w10: v1@2710,3350 2770,3290 v1(2770,2480) ; v1(2735,4240) 2745,4240 IC15.3
NetIC4_2: IC4.2 IC7.10 | length 1002.4
  Top Layer w10: IC7.10 2664,2685 2703.52,2645.47 2703.52,2553.52 2495,2345 2495,2015 2580,1930 IC4.2
NetIC5_2: IC5.2 IC5.13 | length 213.5
  Top Layer w10: IC5.2 IC5.13
NetIC5_3: IC5.3 IC5.5 IC5.10 | length 359.6
  Top Layer w10: IC5.5 1470,2685 ; IC5.3 1400.45,2785 1470,2715.45 1470,2685 ; IC5.10 1470,2685
NetIC5_6: IC5.6 IC6.4 | length 648.9
  Top Layer w10: IC5.6 1400.45,2635 1505.45,2530 1645,2530 1850,2735 IC6.4
NetIC5_8: IC5.8 IC5.9 IC10.3 | length 2020.7
  Top Layer w10: IC5.8 IC5.9 1598.02,2633.75 1673.75,2633.75 1760,2720 1760,4299.25 IC10.3
NetIC5_11: IC5.11 IC5.12 IC9.3 | length 860.9
  Top Layer w10: IC9.3 1190,3177.74 1417.27,2950.47 ; 1414.08,2950.47 1417.27,2950.47 ; IC5.11 IC5.12 1614,2785 1695,2866 1695,2925 1669.53,2950.47 1417.27,2950.47
NetIC6_5: IC6.5 IC6.6 IC11.3 | length 845
  Top Layer w10: IC6.6 IC6.5 1920.92,2685 1990,2754.08 v1(1990,2969.14) v1@1984.14,2975
  Bottom Layer w10: IC11.3 1700.74,3185 1916.6,2969.14 v1(1990,2969.14)
NetIC6_8: IC6.8 IC6.9 IC12.3 | length 693.7
  Top Layer w10: IC6.8 IC6.9 v1(2255,2635)
  Bottom Layer w10: v1(2255,2635) 2255,2795 2390,2930 IC12.3
NetIC6_10: IC6.10 IC7.8 | length 728.5
  Top Layer w10: IC6.10 2305,2685 2305,2515 2559.55,2515 2629.55,2585 IC7.8
NetIC7_1: IC7.1 IC7.12 | length 255
  Top Layer w10: IC7.1 2529.55,2885 2629.55,2785 IC7.12
NetIC7_2: IC7.2 IC7.3 IC14.3 | length 779.1
  Top Layer w10: IC7.3 IC7.2 2416,2835 2335,2916 2335,2954.14 2340.86,2960 2519.96,2960 2644.96,3085 IC14.3
NetIC7_4: IC7.4 IC7.9 IC7.11 | length 367.9
  Top Layer w10: IC7.4 2540,2735 ; IC7.9 2629.55,2635 2540,2724.55 2540,2735 ; IC7.11 2540,2735
NetIC7_5: IC7.5 IC7.6 IC13.3 | length 1930.4
  Top Layer w10: IC13.3 2383.7,4272.58 2310,4198.88 2310,3990.86 2304.14,3985 2230,3985 2195,3950 2195,2906 2416,2685 IC7.5 IC7.6
NetIC8_1: IC8.1 Rs1.1 | length 200
  Top Layer w10: Rs1.1 IC8.1
NetIC8_2: IC8.2 P1.1 | length 312.1
  Top Layer w10: IC8.2 1640,4585 P1.1
NetIC8_4: IC8.4 Rs16.2 | length 200
  Top Layer w10: Rs16.2 IC8.4
NetIC9_1: IC9.1 Rs2.1 | length 332
  Top Layer w10: IC9.1 1451.38,3123.62 1451.38,3251.59 1490,3290.21 Rs2.1
NetIC9_2: IC9.2 P1.2 | length 1603.6
  Top Layer w10: IC9.2 1555,3250 1555,4445 1740,4630 P1.2
NetIC9_4: IC9.4 Rs15.2 | length 314.2
  Top Layer w10: 1140,3130 IC9.4@1190,3080 ; 1140,3135 1140,3307.76 Rs15.2@1190,3357.76
NetIC10_1: IC10.1 Rs3.1 | length 200.3
  Top Layer w10: Rs3.1 1923.46,4334.21 IC10.1
NetIC10_2: IC10.2 P1.3 | length 284.9
  Top Layer w10: P1.3 1840,4519.25 IC10.2
NetIC10_4: IC10.4 Rs14.2 | length 200.7
  Top Layer w10: Rs14.2 1624.25,4136.57 IC10.4
NetIC11_1: IC11.1 Rs4.1 | length 332
  Top Layer w10: IC11.1 1884.06,3123.62 1884.06,3251.59 1922.68,3290.21 Rs4.1
NetIC11_2: IC11.2 P1.4 | length 1536.2
  Top Layer w10: IC11.2 1975,3237.32 1975,4465 1940,4500 P1.4
NetIC11_4: IC11.4 Rs13.2 | length 343.6
  Top Layer w10: IC11.4 1570,3137.68 1570,3235.08 1622.68,3287.76 Rs13.2
NetIC12_1: IC12.1 Rs5.1 | length 200.2
  Top Layer w10: IC12.1 2090.47,3185.47 Rs5.1
NetIC12_2: IC12.2 P1.5 | length 1620.7
  Top Layer w10: P1.5 2040,3135 IC12.2
NetIC12_4: IC12.4 Rs12.2 | length 200
  Top Layer w10: IC12.4 Rs12.2
NetIC13_1: IC13.1 Rs6.1 | length 348
  Bottom Layer w10: IC13.1 2102.32,4416.38 2102.32,4392.68 2145,4350 2145,4189.53 Rs6.1
NetIC13_2: IC13.2 P1.6 | length 373.3
  Top Layer w10: IC13.2 2140,4391.3 P1.6
NetIC13_4: IC13.4 Rs11.2 | length 338.4
  Top Layer w10: IC13.4 2433.23,4385.47 2433.23,4293.82 2390,4250.59 Rs11.2
NetIC14_1: IC14.1 Rs7.1 | length 200
  Top Layer w10: IC14.1 Rs7.1
NetIC14_2: IC14.2 P1.7 | length 1782.3
  Top Layer w10: v1(2240,3925) 2240,3855 2350,3745 2449.14,3745 2465,3729.14 2465,3160 IC14.2
  Bottom Layer w10: v1(2240,3925) P1.7
NetIC14_4: IC14.4 Rs10.2 | length 200
  Top Layer w10: IC14.4 Rs10.2
NetIC15_1: IC15.1 Rs8.1 | length 332
  Top Layer w10: Rs8.1 2540,4229.79 2578.62,4268.41 2578.62,4396.38 IC15.1
NetIC15_2: IC15.2 P1.8 | length 453.3
  Top Layer w10: P1.8 2340,4605 2485,4460 2485,4355 2505,4335 IC15.2
NetIC15_4: IC15.4 Rs9.2 | length 345.6
  Top Layer w10: Rs9.2 2840,4232.24 2785,4287.24 2785,4380 IC15.4
VCC: C2.1 C4.1 C6.1 C8.1 Cs1.1 Cs2.1 D17.2 D18.2 D19.2 D20.2 IC1.1 IC2.1 IC3.1 IC4.1 IC5.14 IC6.14 IC7.14 P2.2 Rs1.2 Rs2.2 Rs3.2 Rs4.2 Rs5.2 Rs6.2 Rs7.2 Rs8.2 Rs9.1 Rs10.1 Rs11.1 Rs12.1 Rs13.1 Rs14.1 Rs15.1 Rs16.1 | length 6650.4
  Top Layer w10: IC1.1 v3(1465,2230) ; IC2.1 1456.88,1845 1558.47,1946.59 1676.59,1946.59 1761.64,2031.64 1761.64,2149.76 1863.23,2251.35 1863.23,2256.57 ; Cs2.1 1503.98,401.02 2038.15,401.02 P2.2 2082.68,585.75 Cs1.1 ; C4.1 1863.23,2256.57 ; C8.1 2346.77,2453.43 C6.1 v3(2020,2256.57) C2.1 1863.23,2256.57 ; IC4.1 2610,1980 2545,2045 2545,2345 v3(2595,2395) IC3.1
  Bottom Layer w10: Rs15.1 Rs2.2 Rs13.1 v4(1835,3685) Rs4.2 Rs5.2 Rs12.1 Rs7.2 Rs10.1 ; Rs16.1 Rs1.2 Rs14.1 v4(1835,3835) Rs3.2 Rs6.2 Rs11.1 Rs8.2 Rs9.1 ; v4@1945,815 2008.43,751.57 Cs1.1
  other v3: 2718.52,2885.96
  other v4: 1950,805
VM: Cs3.1 Cs4.1 D1.1 D2.1 D5.1 D6.1 P2.1 Q1.2 Q2.2 Q5.2 Q6.2 | length 9503.5
  Top Layer w10: Q1.2 D1.1 ; Cs3.1 2173.15,638.43 2173.15,455.08 P2.1 2193.23,435 Cs4.1@2700,435 ; D5.1 3650.39,3035 3680.39,3005 Q5.2
  Bottom Layer w10: Q1.2 255,2810 255,1600 390,1465 530,1465 Q2.2 ; Q2.2@902.5,1117.5 934.01,1085.99 934.01,1057.8 1401.8,590 2015.79,590 2064.21,638.43 2130,638.43 Cs3.1 ; D2.1 2135.55,1010 D6.1 2140.55,756.02 2150.79,745.79 ; 2151.57,741.57 Cs3.1 ; Q5.2 3595,2905 3595,2715 3835,2475 3835,1545 3395,1105 Q6.2 2680,585 2312.82,585 2259.4,638.43 2173.15,638.43 Cs3.1
pads on no net: IC6.1 IC6.2 IC6.3 IC6.11 IC6.12 IC6.13
copper on no net:
  other v3: 1656.59,2885 2117.24,2930.85

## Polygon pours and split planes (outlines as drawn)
no net on Bottom Layer "Bottom GND" (solid, pour order 2): 0,5000 4000,5000 4000,0 0,0
no net on Top Layer "Bottom GND" (solid, pour order 0): 0,0 0,5000 4000,5000 4000,0
no net on VCC (split plane): 3979.9,4974.9 3979.9,20.1 20.1,20.1 20.1,4974.9
no net on GND (split plane): 3979.9,4974.9 3979.9,20.1 20.1,20.1 20.1,4974.9

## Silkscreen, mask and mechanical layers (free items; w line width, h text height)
Top Overlay:
  text "H-Bridge Motor Driver-Team 16" at 1471.99,100 h100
